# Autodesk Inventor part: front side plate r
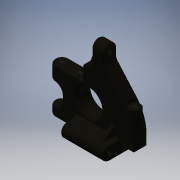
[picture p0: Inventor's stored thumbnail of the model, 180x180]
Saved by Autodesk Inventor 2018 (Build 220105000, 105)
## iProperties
Shininess: 41.0
Compacted: True
Length Units: 11272
Angle Units: 11279
Time Units: 11290
Mass Units: 11286
Length Display Precision: 3
Angle Display Precision: 2
Company: Autodesk
Created: 2001-02
Part Number: front side plate r
Document SubType Name: Modeling
Designer: Autodesk, Inc.
Project: Inventor Samples
Density: 1.28 g/cm^3
Stock Number: front side plate r
Material: Stiffzel
Mass: 15.7207 g
Surface Area: 55.8097 cm^2
Volume: 12.2818 cm^3
Appearance: Stiffzel
Density: 0.0
Volumn: 0.0
Area: 0.0
PropertySet Name: Model Information
Control State: 0
Master: False
Checked Out: False
Author: Autodesk, Inc.
Revision Number: A
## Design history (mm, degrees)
sketch "Sketch1"
  geometry: L1 (-34.263, -17.296)-(16.537, -17.296); L2 (16.537, -17.296)-(16.537, -6.501); L3 (-8.584, 18.544)-(-13.878, 9.374); L4 (-13.878, 9.374)-(-34.263, 9.374); L5 (-34.263, 9.374)-(-34.263, 0.865); L6 (-34.263, 0.865)-(-26.262, 0.865); L7 (-26.262, 0.865)-(-26.262, -11.835); L8 (-26.262, -11.835)-(-34.263, -11.835); L9 (-34.263, -11.835)-(-34.263, -17.296); L10 (10.258, 10.218)-(-1.567, 23.743); L11 (-8.584, 18.544)-(-8.584, 29.059); L12 (-8.584, 29.059)-(-1.567, 29.059); L13 (-1.567, 29.059)-(-1.567, 23.743); A1 r 25.4 centre (-8.863, -6.501) between (16.537, -6.501) and (10.258, 10.218)
  constraints: 26 end point, 6 parallel, 3 perpendicular, 2 point on circle, 2 tangent, 1 centre point, 1 collinear, 1 horizontal, 1 vertical alignment, 1 other
  dimensions: "d0" = 5.461 distance of L8.end L1.start; "d1" = 50.8 distance of L1.start L1.end; "d2" = 25.4 radius of A1; "d5" = 10.795 distance from line of L1 A1.centre; "d7" = 26.67 distance between parallel lines of L1 L4; "d8" = 120 deg angle of L4 L3; "d9" = 8.001 distance between parallel lines of L9 L7; "d10" = 12.7 distance of L6.end L7.end; "d186" = 48.8349 deg angle of L1 L10; "d187" = 25.1207 distance from line of L2 L3.start; "d188" = 7.01675 distance between parallel lines of L13 L11; "d189" = 46.355 distance between parallel lines of L1 L12; "d191" = 9.17024 vertical distance of L3.start L3.end
extrude "Extrusion1" new body sketch "Sketch1" distance "d13" = 8.001; taper "d14" = 0 deg
sketch "Sketch2"
  geometry: L1 (16.537, -17.296)-(-34.263, -17.296) reference; L2 (16.537, -17.296)-(8.536, -17.296); L3 (8.536, -17.296)-(8.536, -12.534); L4 (8.536, -12.534)-(16.537, -12.534); L5 (16.537, -12.534)-(16.537, -17.296)
  constraints: 8 end point, 2 parallel, 1 horizontal, 1 perpendicular
  dimensions: "d15" = 4.7625 distance between parallel lines of L1 L4; "d184" = 8.001 distance between parallel lines of L5 L3
extrude "Extrusion2" cut sketch "Sketch2" extent not by distance; stored distance "d16" = 6.35; taper "d17" = 0 deg
fillet "Fillet1" dims "d18" = 4.0005 (= 0.5 x d13)
sketch "Sketch10"
  geometry: L1 (39.026, 1.373)-(34.263, 9.374) reference; L2 (34.263, 9.374)-(13.878, 9.374) reference; L3 (13.878, 9.374)-(2.513, 29.059) reference; L4 (31.088, 0.865)-(24.675, 0.865) reference; L5 (8.838, 18.105)-(14.07, 18.105); L6 (14.07, 18.105)-(14.07, 9.374)
  constraints: 4 end point, 2 point on line, 1 parallel, 1 perpendicular
  dimensions: "d62" = 8.73125 distance between parallel lines of L5 L2; "d63" = 20.193 distance between parallel lines of L1 L6
extrude "Extrusion9" join sketch "Sketch10" stored distance "d64" = 4.7625; taper "d65" = 0 deg
sketch "Sketch28"
  geometry: L1 (0, 5.316)-(-8.001, 5.316) reference; 1 further point
  constraints: 1 horizontal alignment, 1 midpoint, 2 other
extrude "Extrusion19" join sketch "Sketch28" stored distance "d192" = 25.4; taper "d193" = 0 deg
sketch "Sketch29"
  geometry: L1 (-30.263, 0.865)-(-30.263, 9.374) reference; L2 (-26.262, 0.865)-(-30.263, 0.865) reference; L3 (-26.262, -11.835)-(-26.262, 0.865) reference; L4 (-30.263, -11.835)-(-26.262, -11.835) reference; L5 (-30.263, -17.296)-(-30.263, -11.835) reference; L6 (8.536, -17.296)-(-30.263, -17.296) reference; L7 (8.536, -17.296)-(8.536, -12.534) reference; L8 (8.536, -12.534)-(16.537, -12.534) reference; L9 (16.537, -6.501)-(16.537, -12.534) reference; L10 (-1.567, 23.743)-(10.258, 10.218) reference; L11 (-1.567, 29.059)-(-1.567, 23.743) reference; L12 (-8.584, 29.059)-(-1.567, 29.059) reference; L13 (-8.584, 18.544)-(-8.584, 29.059) reference; L14 (-8.838, 18.105)-(-8.584, 18.544) reference; L15 (-14.07, 18.105)-(-8.838, 18.105) reference; L16 (-14.07, 9.374)-(-14.07, 18.105) reference; L17 (-30.263, 9.374)-(-14.07, 9.374) reference; A1 r 25.4 centre (-8.863, -6.501) between (16.537, -6.501) and (10.258, 10.218) reference; A2 r 5.486 centre (-14.07, 23.591) between (-14.07, 18.105) and (-8.584, 23.591)
  constraints: 3 point on line, 2 point on circle, 2 tangent, 1 centre point
extrude "Extrusion20" join sketch "Sketch29" stored distance "d194" = 25.4; taper "d195" = 0 deg
sketch "Sketch4"
  geometry: L1 (-16.537, -6.501)-(-16.537, -12.534) reference; L2 (-8.536, -17.296)-(30.263, -17.296) reference; C1 r 9.525 at (10.451, 0.039)
  constraints: 1 centre point
  dimensions: "d30" = 17.3355 distance from line of C1.centre L2; "d31" = 19.05 diameter of C1; "d32" = 26.9875 distance from line of C1.centre L1
extrude "Extrusion4" join sketch "Sketch4" distance "d33" = 0.889; taper "d34" = 0 deg
fillet "Fillet12" dims "d49" = 0.8128
sketch "Sketch6"
  geometry: C1 r 9.525 at (0, 0) reference; C2 r 7.938 at (0, 0)
  constraints: 1 centre point, 1 coincident
  dimensions: "d50" = 15.875 diameter of C2
extrude "Extrusion6" cut sketch "Sketch6" distance "d51" = 3.27152; taper "d52" = 0 deg
sketch "Sketch7"
  geometry: C1 r 9.525 at (0, 0) reference; C2 r 6.985 at (0, 0)
  constraints: 1 centre point, 1 coincident
  dimensions: "d53" = 13.97 diameter of C2
extrude "Extrusion7" cut sketch "Sketch7" extent not by distance; stored distance "d54" = 3.27152; taper "d55" = 0 deg
chamfer "Chamfer2" distance "d56" = 1.27; stored, may be unused: second distance "d57" = 1.27, angle "d250" = 45 deg
fillet "Fillet43" dims "d115" = 4.7625
fillet "Fillet44" dims "d116" = 0.8128
fillet "Fillet45" dims "d117" = 0.8128
fillet "Fillet64" dims "d196" = 3.175
fillet "Fillet46" dims "d118" = 0.8128
fillet "Fillet47" dims "d119" = 0.8128
fillet "Fillet48" dims "d120" = 0.381
fillet "Fillet49" dims "d121" = 0.8128
workplane "Work Plane1"
workplane "Work Plane2"
workplane "Work Plane3"
workplane "Work Plane4"
workpoint "Work Point3"
workaxis "Work Axis1"
workplane "Work Plane5"
sketch "Sketch20"
  geometry: L1 (-11.23, 0)-(-6.468, 0) reference; L2 (-11.23, 6.35)-(-11.23, 0); L3 (-3.229, 6.35)-(-3.229, 0); L4 (-3.229, 0)-(-11.23, 0); A1 r 4.001 centre (-7.23, 6.35) between (-11.23, 6.35) and (-3.229, 6.35); 1 further point
  constraints: 6 end point, 2 perpendicular, 2 point on circle, 2 point on line, 2 tangent, 1 centre point, 1 coincident, 1 collinear
  dimensions: "d128" = 8.001 diameter of A1
extrude "Extrusion16" join sketch "Sketch20" stored distance "d129" = 25.4; taper "d130" = 0 deg
fillet "Fillet50" dims "d131" = 0.8128
fillet "Fillet51" dims "d132" = 0.8128
fillet "Fillet52" dims "d133" = 3.175
fillet "Fillet53" dims "d134" = 0.8128
fillet "Fillet54" dims "d135" = 0.8128
fillet "Fillet55" dims "d136" = 0.8128
fillet "Fillet56" dims "d137" = 0.381
sketch "Sketch21"
  geometry: 3 further points
  constraints: 1 other
hole "Hole1" sketch "Sketch21" at (-6.35, -7.23) diameter "d138" = 3.175; stored, may be unused: countersink angle "d142" = 60 deg, drill point angle "d144" = 118 deg; dims "d139" = 12.7, "d140" = 9.525, "d141" = 6.35, "d143" = 19.05
workplane "Work Plane6"
sketch "Sketch22"
  geometry: L1 (-7.166, -2.119)-(-1.617, 1.958)
  constraints: 2 end point
feature "Rib1" sketch "Sketch22" dims "d146" = 2.54, "d147" = 2.54
fillet "Fillet57" dims "d148" = 0.8128
fillet "Fillet58" dims "d149" = 0.8128
workplane "Work Plane7"
sketch "Sketch23" dims "d151" = 6.35
  geometry: L1 (46.799, 0)-(46.799, 6.375) reference; L2 (46.799, 3.188)-(32.274, 3.188); 1 further point
  constraints: 2 end point, 1 horizontal alignment, 1 midpoint, 1 perpendicular, 1 point on line, 2 other
extrude "Extrusion17" join sketch "Sketch23" stored distance "d152" = 25.4; taper "d153" = 0 deg
sketch "Sketch24"
  geometry: C1 r 3.175 at (43.624, -3.188); A1 r 3.175 centre (43.624, -3.188) between (42.181, -6.015) and (42.181, -0.36) reference
  constraints: 1 centre point, 1 coincident
  dimensions: "d154" = 6.35 diameter of C1
extrude "Extrusion18" cut sketch "Sketch24" extent not by distance; stored distance "d155" = 25.4; taper "d156" = 0 deg
fillet "Fillet60" dims "d158" = 0.381
fillet "Fillet62" dims "d160" = 0.381
fillet "Fillet63" dims "d161" = 0.381
sketch "Sketch25"
  geometry: A1 r 2.794 centre (43.624, -3.188) between (43.987, -5.958) and (43.987, -0.417) reference
hole "Hole2" sketch "Sketch25" at (43.624, -3.188) diameter "d162" = 2.159; stored, may be unused: countersink angle "d166" = 60 deg, drill point angle "d168" = 118 deg; dims "d163" = 12.7, "d164" = 9.525, "d165" = 6.35, "d167" = 8.001
workplane "Work Plane8"
sketch "Sketch30"
  geometry: L1 (-29.257, 30.422)-(-25.239, 41.396); A1 r 0.813 centre (-29.794, 29.066) between (-29.899, 29.872) and (-30.607, 29.066) reference; A2 r 0.813 centre (-24.308, 43.967) between (-24.308, 44.78) and (-25.121, 43.967) reference
  constraints: 2 end point
feature "Rib2" sketch "Sketch30" dims "d197" = 2.54, "d198" = 2.54
fillet "Fillet65" dims "d199" = 0.8128
fillet "Fillet66" dims "d200" = 0.8128
sketch "Sketch32"
  geometry: C1 r 2.794 at (-3.188, 5.467); A1 r 3.188 centre (-3.188, 5.467) between (0, 5.467) and (-6.375, 5.467) reference
  constraints: 1 centre point, 1 coincident
  dimensions: "d210" = 5.588 diameter of C1
extrude "Extrusion22" cut sketch "Sketch32" extent not by distance; stored distance "d211" = 1.5875; taper "d212" = 0 deg
sketch "Sketch33"
  geometry: A1 r 2.794 centre (-3.188, 5.467) between (-5.166, 3.494) and (-1.21, 3.494) reference; 1 further point
  constraints: 1 coincident, 3 other
extrude "Extrusion23" cut sketch "Sketch33" distance "d213" = 3.81; taper "d214" = 0 deg
fillet "Fillet69" dims "d215" = 0.381
sketch "Sketch34"
  geometry: C1 r 2.794 at (0, 0) reference
hole "Hole5" sketch "Sketch34" at (0, 0) diameter "d216" = 3.175; stored, may be unused: countersink angle "d220" = 60 deg, drill point angle "d222" = 118 deg; dims "d217" = 12.7, "d218" = 9.525, "d219" = 6.35, "d221" = 19.05
sketch "Sketch35"
  geometry: C1 r 1.587 at (0, -3.188); C2 r 1.587 at (11.049, -3.188); A1 r 3.188 centre (0, -3.188) between (0, 0) and (0, -6.375) reference
  constraints: 2 centre point, 1 concentric, 1 horizontal alignment
  dimensions: "d223" = 11.049 distance of C2.centre A1.centre
hole "Hole6" sketch "Sketch35" at (0, -3.188), (11.049, -3.188) diameter "d224" = 2.159; stored, may be unused: countersink angle "d228" = 60 deg, drill point angle "d230" = 118 deg; dims "d225" = 12.7, "d226" = 9.525, "d227" = 6.35, "d229" = 8.001
body "Solid1"
other parameters: "d123" = -10 deg, "d124" = 0, "d125" = 6.35, "d126" = -4.0005, "d127" = -25.4, "d145" = -12.7, "d150" = -25.4, "d190" = 25.1207 (derived)
